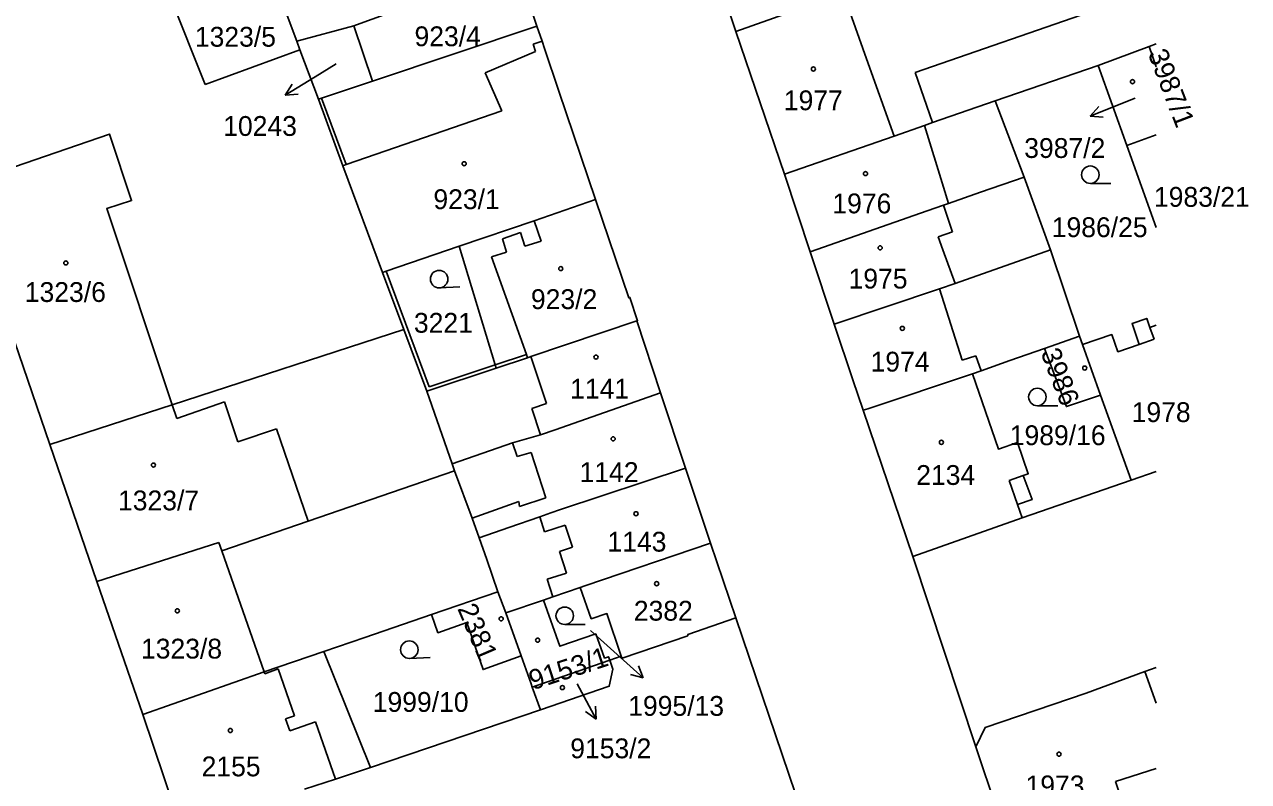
# Model space of a CAD drawing. Extents: x -564952 to -564307, y -1202373 to -1201847.
# Drawn here: x -564411.7 to -564306.7, y -1202086.9 to -1202022 of the extents above; entities that cross this region are included whole.
import ezdxf

# ---------------------------------------------------------------- set-up
doc = ezdxf.new("R2010")
doc.units = 0
for name, color, linetype in [('Hranice parcel', 7, 'Continuous'), ('Parcelní čísla', 7, 'Continuous'), ('Pop  PČ popisy', 7, 'Continuous'), ('Vnitřní kresba', 7, 'Continuous'), ('Značky budov', 7, 'Continuous'), ('Značky kultur', 7, 'Continuous')]:
    doc.layers.add(name, color=color, linetype=linetype)

msp = doc.modelspace()

# ---------------------------------------------------------------- linework, layer by layer
at = {"layer": 'Hranice parcel'}
for p, q in [((-564350.68, -1202022.6), (-564353.91, -1202012.99)), ((-564388.33, -1202023.43), (-564391.22, -1202015.7)), ((-564369.43, -1202017.02), (-564367.73, -1202022.14)), ((-564388.33, -1202023.43), (-564383.43, -1202022.13)), ((-564383.43, -1202022.13), (-564381.84, -1202026.87)), ((-564381.84, -1202026.87), (-564367.73, -1202022.14)), ((-564346.52, -1202034.83), (-564350.68, -1202022.6)), ((-564315.26, -1202023.89), (-564319.63, -1202025.52)), ((-564314.65, -1202023.66), (-564315.26, -1202023.89)), ((-564315.26, -1202023.89), (-564314.65, -1202025.64)), ((-564328.44, -1202028.56), (-564319.63, -1202025.52)), ((-564319.63, -1202025.52), (-564317.17, -1202032.38)), ((-564325.97, -1202035.09), (-564328.44, -1202028.56)), ((-564314.65, -1202031.48), (-564317.17, -1202032.38)), ((-564317.17, -1202032.38), (-564314.65, -1202039.42)), ((-564344.32, -1202041.5), (-564346.52, -1202034.83)), ((-564409.49, -1202058.02), (-564417.13, -1202035.78)), ((-564323.72, -1202041.34), (-564325.97, -1202035.09)), ((-564342.24, -1202047.7), (-564344.32, -1202041.5)), ((-564321.21, -1202048.72), (-564323.72, -1202041.34)), ((-564380.96, -1202043.26), (-564379.14, -1202048.15)), ((-564359.18, -1202047.43), (-564357.14, -1202053.6)), ((-564379.14, -1202048.15), (-564399, -1202054.61)), ((-564377.16, -1202053.45), (-564379.14, -1202048.15)), ((-564324.22, -1202049.78), (-564321.21, -1202048.72)), ((-564321.21, -1202048.72), (-564320.97, -1202049.46)), ((-564320.97, -1202049.46), (-564319.42, -1202053.78)), ((-564371.23, -1202051.48), (-564377.16, -1202053.45)), ((-564375, -1202059.69), (-564377.16, -1202053.45)), ((-564357.14, -1202053.6), (-564354.99, -1202060.04)), ((-564316.8, -1202061.07), (-564319.42, -1202053.78)), ((-564399, -1202054.61), (-564409.49, -1202058.02)), ((-564335.5, -1202067.64), (-564339.78, -1202055.09)), ((-564409.49, -1202058.02), (-564405.45, -1202069.78)), ((-564374.79, -1202060.27), (-564375, -1202059.69)), ((-564354.99, -1202060.04), (-564352.85, -1202066.48)), ((-564373.3, -1202064.33), (-564374.79, -1202060.27)), ((-564326.14, -1202064.32), (-564316.8, -1202061.07)), ((-564316.8, -1202061.07), (-564314.65, -1202060.33)), ((-564372.69, -1202066.04), (-564373.3, -1202064.33)), ((-564372.69, -1202066.04), (-564370.13, -1202065.15)), ((-564335.5, -1202067.64), (-564326.14, -1202064.32)), ((-564395, -1202066.42), (-564405.45, -1202069.78)), ((-564352.85, -1202066.48), (-564350.67, -1202072.89)), ((-564330.1, -1202083.96), (-564335.5, -1202067.64)), ((-564405.45, -1202069.78), (-564401.53, -1202081.18)), ((-564376.76, -1202072.61), (-564371.08, -1202070.67)), ((-564371.08, -1202070.67), (-564370.4, -1202072.46)), ((-564370.4, -1202072.46), (-564367.17, -1202071.36)), ((-564369.09, -1202076.15), (-564370.4, -1202072.46)), ((-564350.67, -1202072.89), (-564345.58, -1202087.99)), ((-564386.01, -1202075.77), (-564381.99, -1202085.72)), ((-564368.14, -1202078.82), (-564361.49, -1202076.51)), ((-564360.5, -1202076.17), (-564361.49, -1202076.51)), ((-564315.61, -1202077.5), (-564314.65, -1202077.16)), ((-564314.65, -1202080.21), (-564315.61, -1202077.5)), ((-564367.44, -1202080.79), (-564368.14, -1202078.82)), ((-564367.44, -1202080.79), (-564381.99, -1202085.72)), ((-564398.11, -1202091.24), (-564401.53, -1202081.18)), ((-564327.05, -1202093.01), (-564330.1, -1202083.96))]:
    msp.add_line(p, q, dxfattribs=at)
for points in [[(-564369.43, -1202017.02), (-564382.88, -1202021.93), (-564383.43, -1202022.13)], [(-564334.61, -1202016.87), (-564340.12, -1202018.83), (-564341.48, -1202019.32), (-564350.68, -1202022.6)], [(-564367.73, -1202022.14), (-564367.3, -1202023.45), (-564367.09, -1202024.07), (-564365.86, -1202027.72), (-564362.71, -1202037.02)], [(-564386.47, -1202028.42), (-564388.06, -1202024.17), (-564388.33, -1202023.43)], [(-564381.84, -1202026.87), (-564386.19, -1202028.32), (-564386.47, -1202028.42)], [(-564386.47, -1202028.42), (-564384.36, -1202034.12), (-564380.96, -1202043.26)], [(-564328.44, -1202028.56), (-564333.81, -1202030.42), (-564334.5, -1202030.66), (-564337.12, -1202031.57), (-564346.52, -1202034.83)], [(-564417.13, -1202035.78), (-564404.38, -1202031.4), (-564402.49, -1202037.11), (-564404.61, -1202037.8), (-564399, -1202054.61)], [(-564325.97, -1202035.09), (-564329.7, -1202036.39), (-564332.45, -1202037.35), (-564332.88, -1202037.5)], [(-564374.39, -1202041.02), (-564367.97, -1202038.83), (-564362.71, -1202037.02)], [(-564362.71, -1202037.02), (-564359.86, -1202045.45), (-564359.77, -1202045.41), (-564359.11, -1202047.41), (-564359.18, -1202047.43)], [(-564332.88, -1202037.5), (-564334.29, -1202037.99), (-564344.32, -1202041.5)], [(-564380.96, -1202043.26), (-564380.67, -1202043.16), (-564374.39, -1202041.02)], [(-564374.39, -1202041.02), (-564371.32, -1202051.19), (-564371.23, -1202051.48)], [(-564323.72, -1202041.34), (-564331.87, -1202044.22), (-564333.22, -1202044.67), (-564342.24, -1202047.7)], [(-564371.23, -1202051.48), (-564368.54, -1202050.58), (-564368.25, -1202050.48), (-564359.18, -1202047.43)], [(-564314.65, -1202047.79), (-564315.19, -1202047.98), (-564315.45, -1202047.21), (-564316.72, -1202047.65), (-564316.1, -1202049.44), (-564317.93, -1202050.07), (-564318.45, -1202048.6), (-564320.97, -1202049.46)], [(-564339.78, -1202055.09), (-564340.65, -1202052.49), (-564342.24, -1202047.7)], [(-564324.22, -1202049.78), (-564327.2, -1202050.83), (-564329.66, -1202051.7), (-564330.39, -1202051.96)], [(-564319.42, -1202053.78), (-564322.34, -1202054.77), (-564324.22, -1202049.78)], [(-564339.78, -1202055.09), (-564339.38, -1202054.96), (-564330.39, -1202051.96)], [(-564330.39, -1202051.96), (-564328.17, -1202058.42), (-564326.54, -1202057.86), (-564325.62, -1202060.53), (-564326.04, -1202060.69), (-564325.28, -1202062.75), (-564326.53, -1202063.18), (-564326.14, -1202064.32)], [(-564375, -1202059.69), (-564369.82, -1202057.88), (-564367.43, -1202057.19), (-564366.16, -1202056.77), (-564357.14, -1202053.6)], [(-564366.54, -1202063.89), (-564365.72, -1202063.6), (-564354.99, -1202060.04)], [(-564374.79, -1202060.27), (-564387.35, -1202064.59), (-564394.75, -1202067.13), (-564395, -1202066.42)], [(-564370.13, -1202065.15), (-564367.49, -1202064.22), (-564366.54, -1202063.89)], [(-564371.08, -1202070.67), (-564372.03, -1202067.88), (-564372.69, -1202066.04)], [(-564364.04, -1202070.29), (-564363.64, -1202070.15), (-564352.85, -1202066.48)], [(-564367.17, -1202071.36), (-564366.37, -1202071.08), (-564364.04, -1202070.29)], [(-564364.04, -1202070.29), (-564363.08, -1202072.97), (-564361.73, -1202072.53), (-564360.5, -1202076.17)], [(-564367.17, -1202071.36), (-564365.78, -1202075.33), (-564362.69, -1202074.26), (-564361.94, -1202076.34), (-564361.59, -1202076.22), (-564361.49, -1202076.51)], [(-564386.01, -1202075.77), (-564382.48, -1202074.57), (-564376.76, -1202072.61)], [(-564376.76, -1202072.61), (-564376.23, -1202074.16), (-564373.75, -1202073.3), (-564372.35, -1202077.33), (-564369.09, -1202076.15)], [(-564350.67, -1202072.89), (-564354.81, -1202074.32), (-564354.8, -1202074.43), (-564360.43, -1202076.34), (-564360.5, -1202076.17)], [(-564401.53, -1202081.18), (-564391.13, -1202077.52), (-564386.01, -1202075.77)], [(-564368.14, -1202078.82), (-564368.24, -1202078.54), (-564369.09, -1202076.15)], [(-564361.49, -1202076.51), (-564361.22, -1202077.28), (-564361.53, -1202078.76), (-564367.44, -1202080.79)], [(-564315.61, -1202077.5), (-564320.65, -1202079.34), (-564329.31, -1202082.28), (-564330.1, -1202083.96)], [(-564381.99, -1202085.72), (-564385, -1202086.73), (-564387.67, -1202087.58)]]:
    msp.add_lwpolyline(points, dxfattribs=at)
at = {"layer": 'Pop  PČ popisy'}
for p, q in [((-564384.96, -1202025.38), (-564386.76, -1202026.49)), ((-564386.76, -1202026.49), (-564389.31, -1202028.08)), ((-564389.31, -1202028.08), (-564388.72, -1202027.12)), ((-564389.31, -1202028.08), (-564388.19, -1202027.97)), ((-564316.46, -1202028.33), (-564317.53, -1202028.75)), ((-564317.53, -1202028.75), (-564320.31, -1202029.87)), ((-564320.31, -1202029.87), (-564319.57, -1202029.03)), ((-564320.31, -1202029.87), (-564319.2, -1202029.96)), ((-564363.13, -1202073.97), (-564360.85, -1202076.03)), ((-564360.85, -1202076.03), (-564358.62, -1202078.04)), ((-564358.62, -1202078.04), (-564359.7, -1202077.74)), ((-564358.62, -1202078.04), (-564359.03, -1202077)), ((-564364.29, -1202078.55), (-564364.08, -1202078.93)), ((-564364.08, -1202078.93), (-564362.67, -1202081.58)), ((-564362.67, -1202081.58), (-564363.58, -1202080.93)), ((-564362.67, -1202081.58), (-564362.7, -1202080.46))]:
    msp.add_line(p, q, dxfattribs=at)
at = {"layer": 'Vnitřní kresba'}
for p, q in [((-564399.49, -1202018.85), (-564396.18, -1202027.14)), ((-564341.48, -1202019.32), (-564340.42, -1202022.3)), ((-564319.62, -1202020.68), (-564335.3, -1202026.12)), ((-564340.42, -1202022.3), (-564339.48, -1202024.94)), ((-564396.18, -1202027.14), (-564388.06, -1202024.17)), ((-564367.85, -1202024.33), (-564372.18, -1202026.14)), ((-564368.06, -1202023.7), (-564367.3, -1202023.45)), ((-564367.85, -1202024.33), (-564368.06, -1202023.7)), ((-564339.48, -1202024.94), (-564337.12, -1202031.57)), ((-564372.18, -1202026.14), (-564370.75, -1202029.4)), ((-564335.3, -1202026.12), (-564333.81, -1202030.42)), ((-564386.19, -1202028.32), (-564384.08, -1202034.02)), ((-564370.75, -1202029.4), (-564384.08, -1202034.02)), ((-564334.5, -1202030.66), (-564332.88, -1202035.95)), ((-564384.08, -1202034.02), (-564384.36, -1202034.12)), ((-564332.88, -1202035.95), (-564332.45, -1202037.35)), ((-564332.88, -1202037.5), (-564332.16, -1202039.65)), ((-564367.97, -1202038.83), (-564367.38, -1202040.58)), ((-564369.15, -1202039.85), (-564370.69, -1202040.4)), ((-564368.78, -1202041.02), (-564369.15, -1202039.85)), ((-564332.11, -1202039.79), (-564333.34, -1202040.22)), ((-564332.16, -1202039.65), (-564332.11, -1202039.79)), ((-564370.69, -1202040.4), (-564370.34, -1202041.52)), ((-564367.38, -1202040.58), (-564368.78, -1202041.02)), ((-564333.34, -1202040.22), (-564332.93, -1202041.33)), ((-564370.34, -1202041.52), (-564371.62, -1202041.93)), ((-564371.62, -1202041.93), (-564368.64, -1202050.3)), ((-564332.93, -1202041.33), (-564331.87, -1202044.22)), ((-564376.98, -1202053.07), (-564380.67, -1202043.16)), ((-564333.22, -1202044.67), (-564331.27, -1202050.8)), ((-564314.83, -1202049), (-564315.19, -1202047.98)), ((-564316.1, -1202049.44), (-564314.83, -1202049)), ((-564368.64, -1202050.3), (-564371.32, -1202051.19)), ((-564368.64, -1202050.3), (-564368.54, -1202050.58)), ((-564368.25, -1202050.48), (-564366.91, -1202054.51)), ((-564331.27, -1202050.8), (-564330.11, -1202050.41)), ((-564330.11, -1202050.41), (-564329.66, -1202051.7)), ((-564371.32, -1202051.19), (-564376.98, -1202053.07)), ((-564399, -1202054.61), (-564398.6, -1202055.8)), ((-564398.6, -1202055.8), (-564394.52, -1202054.37)), ((-564394.52, -1202054.37), (-564393.37, -1202057.8)), ((-564366.91, -1202054.51), (-564368.18, -1202054.93)), ((-564368.18, -1202054.93), (-564367.43, -1202057.19)), ((-564393.37, -1202057.8), (-564390.06, -1202056.69)), ((-564390.06, -1202056.69), (-564387.35, -1202064.59)), ((-564369.82, -1202057.88), (-564369.44, -1202059.04)), ((-564369.44, -1202059.04), (-564368.24, -1202058.71)), ((-564368.24, -1202058.71), (-564366.96, -1202062.61)), ((-564326.04, -1202060.69), (-564327.25, -1202061.11)), ((-564327.25, -1202061.11), (-564326.53, -1202063.18)), ((-564369.3, -1202062.91), (-564373.3, -1202064.33)), ((-564369.22, -1202063.35), (-564369.3, -1202062.91)), ((-564366.96, -1202062.61), (-564369.22, -1202063.35)), ((-564367.49, -1202064.22), (-564367.08, -1202065.5)), ((-564367.08, -1202065.5), (-564365.3, -1202064.93)), ((-564365.3, -1202064.93), (-564364.69, -1202066.84)), ((-564394.75, -1202067.13), (-564391.13, -1202077.52)), ((-564364.69, -1202066.84), (-564365.79, -1202067.19)), ((-564365.79, -1202067.19), (-564365.2, -1202069.05)), ((-564365.2, -1202069.05), (-564366.85, -1202069.57)), ((-564366.85, -1202069.57), (-564366.37, -1202071.08)), ((-564391.13, -1202077.52), (-564391.07, -1202077.68)), ((-564391.07, -1202077.68), (-564389.91, -1202077.27)), ((-564389.91, -1202077.27), (-564388.51, -1202081.29)), ((-564388.51, -1202081.29), (-564389.28, -1202081.55)), ((-564389.28, -1202081.55), (-564388.92, -1202082.59)), ((-564388.92, -1202082.59), (-564386.71, -1202081.82)), ((-564386.71, -1202081.82), (-564385, -1202086.73)), ((-564314.65, -1202085.82), (-564318.14, -1202086.92)), ((-564317.24, -1202089.63), (-564318.14, -1202086.92))]:
    msp.add_line(p, q, dxfattribs=at)
at = {"layer": 'Značky budov'}
for centre in [(-564344.03, -1202025.82), (-564316.68, -1202026.91), (-564373.97, -1202033.95), (-564339.57, -1202034.79), (-564338.31, -1202041.16), (-564408.12, -1202042.45), (-564365.69, -1202042.94), (-564336.41, -1202048.07), (-564362.67, -1202050.53), (-564320.77, -1202051.47), (-564361.2, -1202057.54), (-564333.06, -1202057.84), (-564400.61, -1202059.79), (-564359.24, -1202063.96), (-564357.47, -1202069.96), (-564398.56, -1202072.29), (-564370.8, -1202072.97), (-564367.68, -1202074.8), (-564365.55, -1202078.87), (-564394.02, -1202082.55), (-564322.98, -1202084.58)]:
    msp.add_circle(centre, 0.175, dxfattribs=at)
at = {"layer": 'Značky kultur'}
for p, q in [((-564320.29, -1202035.64), (-564318.54, -1202035.64)), ((-564376.08, -1202044.59), (-564374.33, -1202044.5)), ((-564324.83, -1202054.7), (-564323.08, -1202054.7)), ((-564365.35, -1202073.46), (-564363.6, -1202073.46)), ((-564378.63, -1202076.37), (-564376.89, -1202076.28))]:
    msp.add_line(p, q, dxfattribs=at)
for centre in [(-564320.29, -1202034.89), (-564376.12, -1202043.84), (-564324.83, -1202053.95), (-564365.35, -1202072.71), (-564378.67, -1202075.62)]:
    msp.add_circle(centre, 0.75, dxfattribs=at)

# ---------------------------------------------------------------- texts
at = {"layer": 'Parcelní čísla'}
for s, p in [('1323/5', (-564397.06, -1202023.91)), ('923/4', (-564378.23, -1202023.87)), ('1977', (-564346.57, -1202029.36)), ('10243', (-564394.63, -1202031.56)), ('3987/2', (-564325.96, -1202033.45)), ('1983/21', (-564314.84, -1202037.64)), ('923/1', (-564376.61, -1202037.84)), ('1976', (-564342.41, -1202038.2)), ('1986/25', (-564323.6, -1202040.24)), ('1975', (-564341.02, -1202044.65)), ('1323/6', (-564411.64, -1202045.8)), ('923/2', (-564368.25, -1202046.41)), ('3221', (-564378.28, -1202048.44)), ('1974', (-564339.13, -1202051.77)), ('1141', (-564364.89, -1202054.09)), ('1978', (-564316.75, -1202056.1)), ('1989/16', (-564327.2, -1202058.08)), ('1142', (-564364.08, -1202061.24)), ('2134', (-564335.22, -1202061.49)), ('1323/7', (-564403.65, -1202063.67)), ('1143', (-564361.69, -1202067.21)), ('2382', (-564359.43, -1202073.13)), ('1323/8', (-564401.68, -1202076.38)), ('1999/10', (-564381.81, -1202080.95)), ('1995/13', (-564359.91, -1202081.29)), ('9153/2', (-564364.88, -1202084.93)), ('2155', (-564396.48, -1202086.48)), ('1973', (-564325.85, -1202088.11))]:
    msp.add_text(s, height=1.7, dxfattribs=at).set_placement(p)
for s, rotation, p in [('3987/1', 291, (-564315.38, -1202024.49)), ('3986', 291, (-564324.57, -1202050.14)), ('2381', 293, (-564374.58, -1202072.09)), ('9153/1', 18, (-564368.09, -1202079.1))]:
    msp.add_text(s, height=1.7, rotation=rotation, dxfattribs=at).set_placement(p)

doc.saveas('drawing.dxf')
